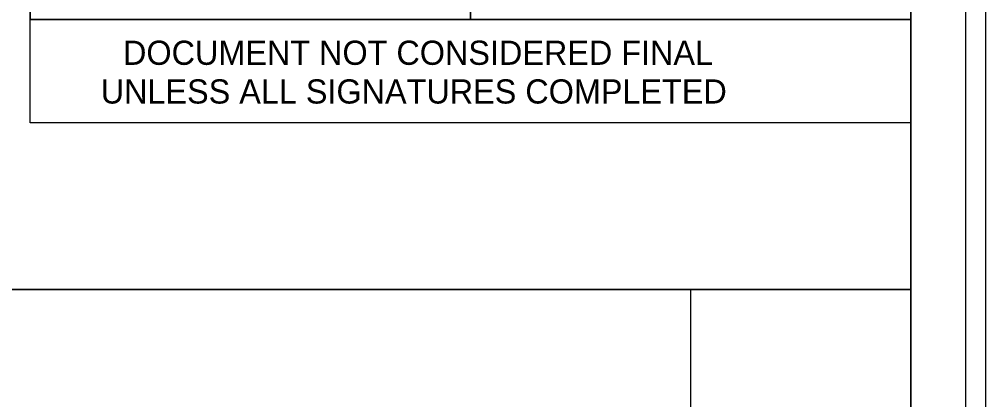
# Model space of a CAD drawing. Extents: x 1640342 to 1730599, y 538663 to 843747.
# Drawn here: x 1730133.49 to 1730177.39, y 540030.55 to 540047.85 of the extents above; entities that cross this region are included whole.
import ezdxf

# ---------------------------------------------------------------- set-up
doc = ezdxf.new("R2010")
doc.units = 0
for name, color, linetype in [('Sheet Clip Boundary CELL', 7, 'Continuous'), ('Sheet Layout Plan Border', 7, 'Continuous'), ('Sheet Plan CELL', 7, 'Continuous'), ('Sheet Plan Layout CELL', 7, 'Continuous'), ('Sheet Plot Border Inside CELL', 7, 'Continuous'), ('Sheet Plot Border Outside CELL', 7, 'Continuous'), ('Sheet Sticker Exception Certification CELL', 7, 'Continuous')]:
    doc.layers.add(name, color=color, linetype=linetype)

msp = doc.modelspace()

# ---------------------------------------------------------------- linework, layer by layer
at = {"layer": 'Sheet Clip Boundary CELL'}
msp.add_lwpolyline([(1729883.99, 539867.862), (1730163.993, 539867.862), (1730163.993, 540035.564), (1730126.14, 540035.564), (1730126.14, 540077.862), (1729883.99, 540077.862)], close=True, dxfattribs=at)
at = {"layer": 'Sheet Layout Plan Border'}
msp.add_lwpolyline([(1729883.99, 539867.862), (1730163.993, 539867.862), (1730163.993, 540035.564), (1730126.14, 540035.564), (1730126.14, 540077.862), (1729883.99, 540077.862)], close=True, dxfattribs=at)
at = {"layer": 'Sheet Plan CELL'}
for points in [[(1729873.99, 539867.862), (1729873.985, 540077.857), (1730133.983, 540077.864), (1730133.985, 540047.852), (1730173.993, 540047.849), (1730173.993, 539867.862)], [(1730173.998, 540077.862), (1729873.99, 540077.862), (1729873.99, 539867.862), (1730173.993, 539867.862)], [(1730133.983, 540070.349), (1730153.993, 540070.349), (1730153.993, 540047.847), (1730133.985, 540047.852)], [(1730153.993, 540070.349), (1730173.99, 540070.352), (1730173.993, 540047.849), (1730153.993, 540047.847)]]:
    msp.add_lwpolyline(points, close=True, dxfattribs=at)
at = {"layer": 'Sheet Plan Layout CELL'}
for points in [[(1729873.985, 540077.857), (1729873.99, 539867.862), (1730173.99, 539867.862), (1730173.99, 540035.564), (1730126.14, 540035.564), (1730126.14, 540077.862)], [(1730126.14, 540035.564), (1730173.995, 540035.564), (1730174, 540077.862), (1730126.14, 540077.862)]]:
    msp.add_lwpolyline(points, close=True, dxfattribs=at)
at = {"layer": 'Sheet Plot Border Inside CELL'}
msp.add_lwpolyline([(1729843.293, 539867.359), (1730176.49, 539867.362), (1730176.493, 540078.359), (1729843.293, 540078.359)], close=True, dxfattribs=at)
at = {"layer": 'Sheet Plot Border Outside CELL'}
msp.add_lwpolyline([(1729840.693, 539863.359), (1730177.393, 539863.359), (1730177.393, 540082.359), (1729840.693, 540082.359)], close=True, dxfattribs=at)
at = {"layer": 'Sheet Sticker Exception Certification CELL'}
for p, q in [((1730133.985, 540043.152), (1730133.985, 540047.852)), ((1730133.985, 540047.852), (1730173.993, 540047.852)), ((1730133.985, 540043.152), (1730133.985, 540047.852)), ((1730133.985, 540047.852), (1730173.993, 540047.852)), ((1730173.993, 540047.849), (1730173.993, 540043.149)), ((1730173.993, 540047.849), (1730173.993, 540043.149)), ((1730173.993, 540043.152), (1730133.985, 540043.152)), ((1730173.993, 540043.152), (1730133.985, 540043.152))]:
    msp.add_line(p, q, dxfattribs=at)

# ---------------------------------------------------------------- texts
for s, p in [('DOCUMENT NOT CONSIDERED FINAL', (1730138.199, 540045.783)), ('DOCUMENT NOT CONSIDERED FINAL', (1730138.199, 540045.783)), ('UNLESS ALL SIGNATURES COMPLETED', (1730137.185, 540044.023)), ('UNLESS ALL SIGNATURES COMPLETED', (1730137.185, 540044.023))]:
    msp.add_text(s, height=1.1, dxfattribs=at).set_placement(p)

doc.saveas('drawing.dxf')
